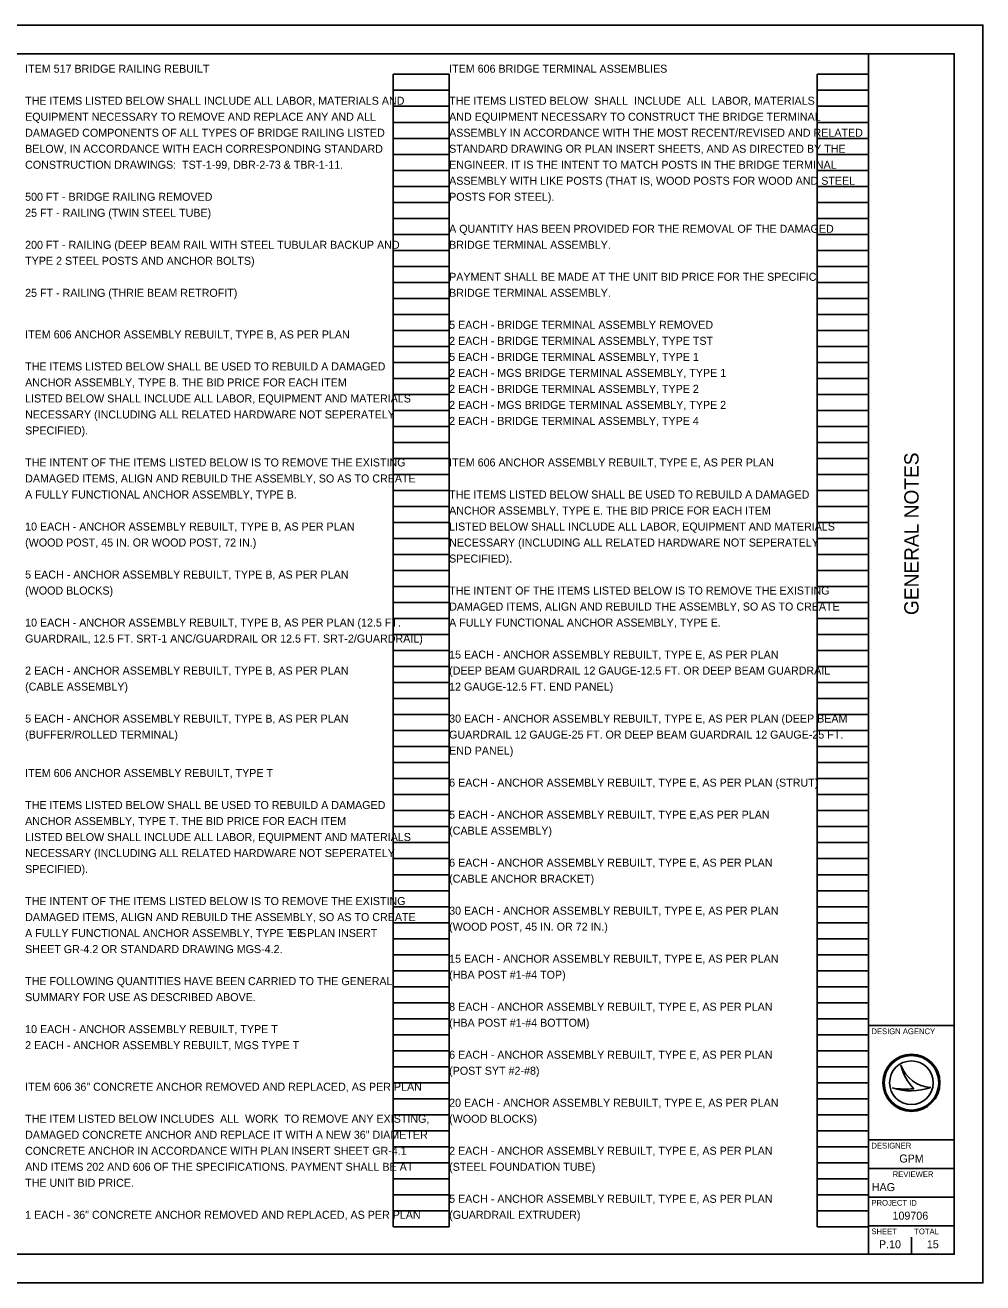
# Model space of a CAD drawing. Extents: x 0 to 34, y 0 to 22.
# Drawn here: x 17.24 to 34, y 0 to 22 of the extents above; entities that cross this region are included whole.
import ezdxf

# ---------------------------------------------------------------- set-up
doc = ezdxf.new("R2010")
doc.units = 0
for name, color, linetype in [('SH_Border', 7, 'Continuous'), ('SH_Cut_Line', 7, 'Continuous'), ('SH_Data', 7, 'Continuous'), ('SH_Text', 7, 'Continuous')]:
    doc.layers.add(name, color=color, linetype=linetype)

msp = doc.modelspace()

# ---------------------------------------------------------------- linework, layer by layer
at = {"layer": 'SH_Border'}
for p, q in [((32, 0.5), (32, 21.5)), ((32, 4.5), (33.5, 4.5)), ((32, 2.5), (33.5, 2.5)), ((32, 2), (33.5, 2)), ((32, 1.5), (33.5, 1.5)), ((32, 1), (33.5, 1))]:
    msp.add_line(p, q, dxfattribs=at)
msp.add_lwpolyline([(1.5, 21.5), (33.5, 21.5), (33.5, 0.5), (1.5, 0.5)], close=True, dxfattribs=at)
at = {"layer": 'SH_Cut_Line'}
msp.add_lwpolyline([(0, 0), (34, 0), (34, 22), (0, 22)], close=True, dxfattribs=at)
at = {"layer": 'SH_Data'}
for p, q in [((23.68, 0.98), (23.68, 21.14)), ((23.68, 21.14), (24.66, 21.14)), ((24.66, 0.98), (24.66, 21.14)), ((31.1, 0.98), (31.1, 21.14)), ((31.1, 21.14), (32, 21.14)), ((32, 0.98), (32, 21.14)), ((23.68, 20.86), (24.66, 20.86)), ((31.1, 20.86), (32, 20.86)), ((23.68, 20.58), (24.66, 20.58)), ((31.1, 20.58), (32, 20.58)), ((23.68, 20.3), (24.66, 20.3)), ((31.1, 20.3), (32, 20.3)), ((23.68, 20.02), (24.66, 20.02)), ((31.1, 20.02), (32, 20.02)), ((23.68, 19.74), (24.66, 19.74)), ((31.1, 19.74), (32, 19.74)), ((23.68, 19.46), (24.66, 19.46)), ((31.1, 19.46), (32, 19.46)), ((23.68, 19.18), (24.66, 19.18)), ((31.1, 19.18), (32, 19.18)), ((23.68, 18.9), (24.66, 18.9)), ((31.1, 18.9), (32, 18.9)), ((23.68, 18.62), (24.66, 18.62)), ((31.1, 18.62), (32, 18.62)), ((23.68, 18.34), (24.66, 18.34)), ((31.1, 18.34), (32, 18.34)), ((23.68, 18.06), (24.66, 18.06)), ((31.1, 18.06), (32, 18.06)), ((23.68, 17.78), (24.66, 17.78)), ((31.1, 17.78), (32, 17.78)), ((23.68, 17.5), (24.66, 17.5)), ((31.1, 17.5), (32, 17.5)), ((23.68, 17.22), (24.66, 17.22)), ((31.1, 17.22), (32, 17.22)), ((23.68, 16.94), (24.66, 16.94)), ((31.1, 16.94), (32, 16.94)), ((23.68, 16.66), (24.66, 16.66)), ((31.1, 16.66), (32, 16.66)), ((23.68, 16.38), (24.66, 16.38)), ((31.1, 16.38), (32, 16.38)), ((23.68, 16.1), (24.66, 16.1)), ((31.1, 16.1), (32, 16.1)), ((23.68, 15.82), (24.66, 15.82)), ((31.1, 15.82), (32, 15.82)), ((23.68, 15.54), (24.66, 15.54)), ((31.1, 15.54), (32, 15.54)), ((23.68, 15.26), (24.66, 15.26)), ((31.1, 15.26), (32, 15.26)), ((23.68, 14.98), (24.66, 14.98)), ((31.1, 14.98), (32, 14.98)), ((23.68, 14.7), (24.66, 14.7)), ((31.1, 14.7), (32, 14.7)), ((23.68, 14.42), (24.66, 14.42)), ((31.1, 14.42), (32, 14.42)), ((23.68, 14.14), (24.66, 14.14)), ((31.1, 14.14), (32, 14.14)), ((23.68, 13.86), (24.66, 13.86)), ((31.1, 13.86), (32, 13.86)), ((23.68, 13.58), (24.66, 13.58)), ((31.1, 13.58), (32, 13.58)), ((23.68, 13.3), (24.66, 13.3)), ((31.1, 13.3), (32, 13.3)), ((23.68, 13.02), (24.66, 13.02)), ((31.1, 13.02), (32, 13.02)), ((23.68, 12.74), (24.66, 12.74)), ((31.1, 12.74), (32, 12.74)), ((23.68, 12.46), (24.66, 12.46)), ((31.1, 12.46), (32, 12.46)), ((23.68, 12.18), (24.66, 12.18)), ((31.1, 12.18), (32, 12.18)), ((23.68, 11.9), (24.66, 11.9)), ((31.1, 11.9), (32, 11.9)), ((23.68, 11.62), (24.66, 11.62)), ((31.1, 11.62), (32, 11.62)), ((23.68, 11.34), (24.66, 11.34)), ((31.1, 11.34), (32, 11.34)), ((23.68, 11.06), (24.66, 11.06)), ((31.1, 11.06), (32, 11.06)), ((23.68, 10.78), (24.66, 10.78)), ((31.1, 10.78), (32, 10.78)), ((23.68, 10.5), (24.66, 10.5)), ((31.1, 10.5), (32, 10.5)), ((23.68, 10.22), (24.66, 10.22)), ((31.1, 10.22), (32, 10.22)), ((23.68, 9.94), (24.66, 9.94)), ((31.1, 9.94), (32, 9.94)), ((23.68, 9.66), (24.66, 9.66)), ((31.1, 9.66), (32, 9.66)), ((23.68, 9.38), (24.66, 9.38)), ((31.1, 9.38), (32, 9.38)), ((23.68, 9.1), (24.66, 9.1)), ((31.1, 9.1), (32, 9.1)), ((23.68, 8.82), (24.66, 8.82)), ((31.1, 8.82), (32, 8.82)), ((23.68, 8.54), (24.66, 8.54)), ((31.1, 8.54), (32, 8.54)), ((23.68, 8.26), (24.66, 8.26)), ((31.1, 8.26), (32, 8.26)), ((23.68, 7.98), (24.66, 7.98)), ((31.1, 7.98), (32, 7.98)), ((23.68, 7.7), (24.66, 7.7)), ((31.1, 7.7), (32, 7.7)), ((23.68, 7.42), (24.66, 7.42)), ((31.1, 7.42), (32, 7.42)), ((23.68, 7.14), (24.66, 7.14)), ((31.1, 7.14), (32, 7.14)), ((23.68, 6.86), (24.66, 6.86)), ((31.1, 6.86), (32, 6.86)), ((23.68, 6.58), (24.66, 6.58)), ((31.1, 6.58), (32, 6.58)), ((23.68, 6.3), (24.66, 6.3)), ((31.1, 6.3), (32, 6.3)), ((23.68, 6.02), (24.66, 6.02)), ((31.1, 6.02), (32, 6.02)), ((23.68, 5.74), (24.66, 5.74)), ((31.1, 5.74), (32, 5.74)), ((23.68, 5.46), (24.66, 5.46)), ((31.1, 5.46), (32, 5.46)), ((23.68, 5.18), (24.66, 5.18)), ((31.1, 5.18), (32, 5.18)), ((23.68, 4.9), (24.66, 4.9)), ((31.1, 4.9), (32, 4.9)), ((23.68, 4.62), (24.66, 4.62)), ((31.1, 4.62), (32, 4.62)), ((23.68, 4.34), (24.66, 4.34)), ((31.1, 4.34), (32, 4.34)), ((23.68, 4.06), (24.66, 4.06)), ((31.1, 4.06), (32, 4.06)), ((23.68, 3.78), (24.66, 3.78)), ((31.1, 3.78), (32, 3.78)), ((32.567, 3.81), (32.567, 3.81)), ((23.68, 3.5), (24.66, 3.5)), ((31.1, 3.5), (32, 3.5)), ((32.417, 3.41), (32.417, 3.41)), ((32.75, 3.5), (32.75, 3.5)), ((33.087, 3.419), (33.087, 3.419)), ((23.68, 3.22), (24.66, 3.22)), ((31.1, 3.22), (32, 3.22)), ((23.68, 2.94), (24.66, 2.94)), ((31.1, 2.94), (32, 2.94)), ((23.68, 2.66), (24.66, 2.66)), ((31.1, 2.66), (32, 2.66)), ((23.68, 2.38), (24.66, 2.38)), ((31.1, 2.38), (32, 2.38)), ((23.68, 2.1), (24.66, 2.1)), ((31.1, 2.1), (32, 2.1)), ((23.68, 1.82), (24.66, 1.82)), ((31.1, 1.82), (32, 1.82)), ((23.68, 1.54), (24.66, 1.54)), ((31.1, 1.54), (32, 1.54)), ((23.68, 1.26), (24.66, 1.26)), ((31.1, 1.26), (32, 1.26)), ((23.68, 0.98), (24.66, 0.98)), ((31.1, 0.98), (32, 0.98)), ((32.375, 0.675), (32.375, 0.675)), ((32.75, 0.5), (32.75, 0.8))]:
    msp.add_line(p, q, dxfattribs=at)
for radius in [0.5, 0.477, 0.477, 0.382]:
    msp.add_circle((32.75, 3.5), radius, dxfattribs=at)
for centre, radius, start, end in [((33.116, 3.998), 0.58, 198.9257, 198.9319), ((33.347, 3.97), 0.796, 191.6379, 191.6421), ((33.116, 3.998), 0.58, 198.9319, 267.1657), ((33.347, 3.97), 0.796, 191.6421, 226.0947), ((32.739, 4.37), 1.013, 251.4576, 290.0832), ((32.648, 4.654), 1.266, 259.4964, 259.4995), ((32.739, 4.37), 1.013, 251.4527, 251.4576), ((32.648, 4.654), 1.266, 259.4995, 276.6672)]:
    msp.add_arc(centre, radius, start, end, dxfattribs=at)

# ---------------------------------------------------------------- texts
msp.add_text('GENERAL NOTES', height=0.25, rotation=90, dxfattribs=at).set_placement((32.875, 11.682))
for s, height, p in [('DESIGN AGENCY', 0.1, (32.05, 4.35)), ('DESIGNER', 0.1, (32.05, 2.35)), ('GPM', 0.14, (32.538, 2.105)), ('REVIEWER', 0.1, (32.422, 1.85)), ('HAG', 0.14, (32.057, 1.605)), ('PROJECT ID', 0.1, (32.05, 1.35)), ('109706', 0.14, (32.419, 1.105)), ('SHEET', 0.1, (32.05, 0.85)), ('TOTAL', 0.1, (32.8, 0.85)), ('P.10', 0.14, (32.182, 0.605)), ('15', 0.14, (33.02, 0.605))]:
    msp.add_text(s, height=height, dxfattribs=at).set_placement(p)
at = {"layer": 'SH_Text'}
for s, p in [('ITEM 517 BRIDGE RAILING REBUILT', (17.24, 21.168)), ('ITEM 606 BRIDGE TERMINAL ASSEMBLIES', (24.66, 21.168)), ('THE ITEMS LISTED BELOW SHALL INCLUDE ALL LABOR, MATERIALS AND', (17.24, 20.608)), ('THE ITEMS LISTED BELOW  SHALL  INCLUDE  ALL  LABOR, MATERIALS', (24.66, 20.608)), ('EQUIPMENT NECESSARY TO REMOVE AND REPLACE ANY AND ALL', (17.24, 20.328)), ('AND EQUIPMENT NECESSARY TO CONSTRUCT THE BRIDGE TERMINAL', (24.66, 20.328)), ('DAMAGED COMPONENTS OF ALL TYPES OF BRIDGE RAILING LISTED', (17.24, 20.048)), ('ASSEMBLY IN ACCORDANCE WITH THE MOST RECENT/REVISED AND RELATED', (24.66, 20.048)), ('BELOW, IN ACCORDANCE WITH EACH CORRESPONDING STANDARD', (17.24, 19.768)), ('STANDARD DRAWING OR PLAN INSERT SHEETS, AND AS DIRECTED BY THE', (24.66, 19.768)), ('CONSTRUCTION DRAWINGS:  TST-1-99, DBR-2-73 & TBR-1-11.', (17.24, 19.488)), ('ENGINEER. IT IS THE INTENT TO MATCH POSTS IN THE BRIDGE TERMINAL', (24.66, 19.488)), ('ASSEMBLY WITH LIKE POSTS (THAT IS, WOOD POSTS FOR WOOD AND STEEL', (24.66, 19.208)), ('500 FT - BRIDGE RAILING REMOVED', (17.24, 18.928)), ('POSTS FOR STEEL).', (24.66, 18.928)), ('25 FT - RAILING (TWIN STEEL TUBE)', (17.24, 18.648)), ('A QUANTITY HAS BEEN PROVIDED FOR THE REMOVAL OF THE DAMAGED', (24.66, 18.368)), ('200 FT - RAILING (DEEP BEAM RAIL WITH STEEL TUBULAR BACKUP AND ', (17.24, 18.088)), ('BRIDGE TERMINAL ASSEMBLY.', (24.66, 18.088)), ('TYPE 2 STEEL POSTS AND ANCHOR BOLTS)', (17.24, 17.808)), ('PAYMENT SHALL BE MADE AT THE UNIT BID PRICE FOR THE SPECIFIC', (24.66, 17.528)), ('25 FT - RAILING (THRIE BEAM RETROFIT)', (17.24, 17.248)), ('BRIDGE TERMINAL ASSEMBLY.', (24.66, 17.248)), ('5 EACH - BRIDGE TERMINAL ASSEMBLY REMOVED', (24.66, 16.688)), ('ITEM 606 ANCHOR ASSEMBLY REBUILT, TYPE B, AS PER PLAN', (17.24, 16.52)), ('2 EACH - BRIDGE TERMINAL ASSEMBLY, TYPE TST', (24.66, 16.408)), ('THE ITEMS LISTED BELOW SHALL BE USED TO REBUILD A DAMAGED', (17.24, 15.96)), ('5 EACH - BRIDGE TERMINAL ASSEMBLY, TYPE 1', (24.66, 16.128)), ('2 EACH - MGS BRIDGE TERMINAL ASSEMBLY, TYPE 1', (24.66, 15.848)), ('ANCHOR ASSEMBLY, TYPE B. THE BID PRICE FOR EACH ITEM', (17.24, 15.68)), ('2 EACH - BRIDGE TERMINAL ASSEMBLY, TYPE 2', (24.66, 15.568)), ('LISTED BELOW SHALL INCLUDE ALL LABOR, EQUIPMENT AND MATERIALS', (17.24, 15.4)), ('2 EACH - MGS BRIDGE TERMINAL ASSEMBLY, TYPE 2', (24.66, 15.288)), ('NECESSARY (INCLUDING ALL RELATED HARDWARE NOT SEPERATELY', (17.24, 15.12)), ('SPECIFIED).', (17.24, 14.84)), ('2 EACH - BRIDGE TERMINAL ASSEMBLY, TYPE 4', (24.66, 15.008)), ('THE INTENT OF THE ITEMS LISTED BELOW IS TO REMOVE THE EXISTING', (17.24, 14.28)), ('ITEM 606 ANCHOR ASSEMBLY REBUILT, TYPE E, AS PER PLAN', (24.66, 14.28)), ('DAMAGED ITEMS, ALIGN AND REBUILD THE ASSEMBLY, SO AS TO CREATE', (17.24, 14)), ('A FULLY FUNCTIONAL ANCHOR ASSEMBLY, TYPE B. ', (17.24, 13.72)), ('THE ITEMS LISTED BELOW SHALL BE USED TO REBUILD A DAMAGED', (24.66, 13.72)), ('ANCHOR ASSEMBLY, TYPE E. THE BID PRICE FOR EACH ITEM', (24.66, 13.44)), ('10 EACH - ANCHOR ASSEMBLY REBUILT, TYPE B, AS PER PLAN', (17.24, 13.16)), ('LISTED BELOW SHALL INCLUDE ALL LABOR, EQUIPMENT AND MATERIALS', (24.66, 13.16)), ('(WOOD POST, 45 IN. OR WOOD POST, 72 IN.)', (17.24, 12.88)), ('NECESSARY (INCLUDING ALL RELATED HARDWARE NOT SEPERATELY', (24.66, 12.88)), ('SPECIFIED).', (24.66, 12.6)), ('5 EACH - ANCHOR ASSEMBLY REBUILT, TYPE B, AS PER PLAN', (17.24, 12.32)), ('(WOOD BLOCKS)', (17.24, 12.04)), ('THE INTENT OF THE ITEMS LISTED BELOW IS TO REMOVE THE EXISTING', (24.66, 12.04)), ('DAMAGED ITEMS, ALIGN AND REBUILD THE ASSEMBLY, SO AS TO CREATE', (24.66, 11.76)), ('10 EACH - ANCHOR ASSEMBLY REBUILT, TYPE B, AS PER PLAN (12.5 FT.', (17.24, 11.48)), ('A FULLY FUNCTIONAL ANCHOR ASSEMBLY, TYPE E.', (24.66, 11.48)), ('GUARDRAIL, 12.5 FT. SRT-1 ANC/GUARDRAIL OR 12.5 FT. SRT-2/GUARDRAIL)', (17.24, 11.2)), ('15 EACH - ANCHOR ASSEMBLY REBUILT, TYPE E, AS PER PLAN', (24.66, 10.92)), ('2 EACH - ANCHOR ASSEMBLY REBUILT, TYPE B, AS PER PLAN', (17.24, 10.64)), ('(DEEP BEAM GUARDRAIL 12 GAUGE-12.5 FT. OR DEEP BEAM GUARDRAIL', (24.66, 10.64)), ('(CABLE ASSEMBLY)', (17.24, 10.36)), ('12 GAUGE-12.5 FT. END PANEL)', (24.66, 10.36)), ('5 EACH - ANCHOR ASSEMBLY REBUILT, TYPE B, AS PER PLAN', (17.24, 9.8)), ('30 EACH - ANCHOR ASSEMBLY REBUILT, TYPE E, AS PER PLAN (DEEP BEAM', (24.66, 9.8)), ('(BUFFER/ROLLED TERMINAL)', (17.24, 9.52)), ('GUARDRAIL 12 GAUGE-25 FT. OR DEEP BEAM GUARDRAIL 12 GAUGE-25 FT.', (24.66, 9.52)), ('END PANEL)', (24.66, 9.24)), ('ITEM 606 ANCHOR ASSEMBLY REBUILT, TYPE T', (17.24, 8.848)), ('6 EACH - ANCHOR ASSEMBLY REBUILT, TYPE E, AS PER PLAN (STRUT)', (24.66, 8.68)), ('THE ITEMS LISTED BELOW SHALL BE USED TO REBUILD A DAMAGED', (17.24, 8.288)), ('ANCHOR ASSEMBLY, TYPE T. THE BID PRICE FOR EACH ITEM', (17.24, 8.008)), ('5 EACH - ANCHOR ASSEMBLY REBUILT, TYPE E,AS PER PLAN', (24.66, 8.12)), ('(CABLE ASSEMBLY)', (24.66, 7.84)), ('LISTED BELOW SHALL INCLUDE ALL LABOR, EQUIPMENT AND MATERIALS', (17.24, 7.728)), ('NECESSARY (INCLUDING ALL RELATED HARDWARE NOT SEPERATELY', (17.24, 7.448)), ('SPECIFIED).', (17.24, 7.168)), ('6 EACH - ANCHOR ASSEMBLY REBUILT, TYPE E, AS PER PLAN', (24.66, 7.28)), ('(CABLE ANCHOR BRACKET)', (24.66, 7)), ('THE INTENT OF THE ITEMS LISTED BELOW IS TO REMOVE THE EXISTING', (17.24, 6.608)), ('DAMAGED ITEMS, ALIGN AND REBUILD THE ASSEMBLY, SO AS TO CREATE', (17.24, 6.328)), ('30 EACH - ANCHOR ASSEMBLY REBUILT, TYPE E, AS PER PLAN', (24.66, 6.44)), ('A FULLY FUNCTIONAL ANCHOR ASSEMBLY, TYPE T. S', (17.24, 6.048)), ('EE PLAN INSERT', (21.873, 6.048)), ('(WOOD POST, 45 IN. OR 72 IN.)', (24.66, 6.16)), ('SHEET GR-4.2 OR STANDARD DRAWING MGS-4.2.', (17.24, 5.768)), ('15 EACH - ANCHOR ASSEMBLY REBUILT, TYPE E, AS PER PLAN', (24.66, 5.6)), ('THE FOLLOWING QUANTITIES HAVE BEEN CARRIED TO THE GENERAL', (17.24, 5.208)), ('(HBA POST #1-#4 TOP)', (24.66, 5.32)), ('SUMMARY FOR USE AS DESCRIBED ABOVE.  ', (17.24, 4.928)), ('8 EACH - ANCHOR ASSEMBLY REBUILT, TYPE E, AS PER PLAN', (24.66, 4.76)), ('(HBA POST #1-#4 BOTTOM)', (24.66, 4.48)), ('10 EACH - ANCHOR ASSEMBLY REBUILT, TYPE T ', (17.24, 4.368)), ('2 EACH - ANCHOR ASSEMBLY REBUILT, MGS TYPE T', (17.24, 4.088)), ('6 EACH - ANCHOR ASSEMBLY REBUILT, TYPE E, AS PER PLAN', (24.66, 3.92)), ('(POST SYT #2-#8)', (24.66, 3.64)), ('ITEM 606 36" CONCRETE ANCHOR REMOVED AND REPLACED, AS PER PLAN', (17.24, 3.36)), ('20 EACH - ANCHOR ASSEMBLY REBUILT, TYPE E, AS PER PLAN', (24.66, 3.08)), ('THE ITEM LISTED BELOW INCLUDES  ALL  WORK  TO REMOVE ANY EXISTING,', (17.24, 2.8)), ('(WOOD BLOCKS)', (24.66, 2.8)), ('DAMAGED CONCRETE ANCHOR AND REPLACE IT WITH A NEW 36" DIAMETER', (17.24, 2.52)), ('CONCRETE ANCHOR IN ACCORDANCE WITH PLAN INSERT SHEET GR-4.1', (17.24, 2.24)), ('2 EACH - ANCHOR ASSEMBLY REBUILT, TYPE E, AS PER PLAN', (24.66, 2.24)), ('AND ITEMS 202 AND 606 OF THE SPECIFICATIONS. PAYMENT SHALL BE AT', (17.24, 1.96)), ('(STEEL FOUNDATION TUBE)', (24.66, 1.96)), ('THE UNIT BID PRICE.', (17.24, 1.68)), ('5 EACH - ANCHOR ASSEMBLY REBUILT, TYPE E, AS PER PLAN', (24.66, 1.4)), ('1 EACH - 36" CONCRETE ANCHOR REMOVED AND REPLACED, AS PER PLAN', (17.24, 1.12)), ('(GUARDRAIL EXTRUDER)', (24.66, 1.12))]:
    msp.add_text(s, height=0.14, dxfattribs=at).set_placement(p)

doc.saveas('drawing.dxf')
